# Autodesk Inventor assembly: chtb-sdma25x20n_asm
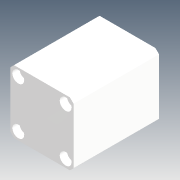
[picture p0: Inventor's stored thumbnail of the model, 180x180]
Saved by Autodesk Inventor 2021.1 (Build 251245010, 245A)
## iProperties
Company: Microsoft
Created: 2018-05
Part Number: chtb-sdma25x20n_asm
Description: STEP AP214
Document SubType Name: Assembly
Designer: user
Title: chtb-sdma25x20n_asm.STEP
Author: Windows
Revision Number: ÈÎºÎ
Sending System: SolidWorks 2015
Preprocessor: SwSTEP 2.0
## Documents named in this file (4)
- D:\Vault_2016\Projekty\Clamptek\Hydraulic\CHTB\CHTB-25\Inventor\chtb-sdma25x20n\chtb-sdma25x20n_asm.iam
- D:\Vault_2016\Projekty\Clamptek\Hydraulic\CHTB\CHTB-25\Inventor\chtb-sdma25x20n\CHTB-25QG.ipt
- D:\Vault_2016\Projekty\Clamptek\Hydraulic\CHTB\CHTB-25\Inventor\chtb-sdma25x20n\CHTB-SDMA25X20NBT.ipt
- D:\Vault_2016\Projekty\Clamptek\Hydraulic\CHTB\CHTB-25\Inventor\chtb-sdma25x20n\CHTB-SDMA25X20NHSG.ipt
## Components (3 placed, 3 different names)
1. CHTB-25QG_1
2. CHTB-SDMA25X20NBT_2
3. CHTB-SDMA25X20NHSG_3
